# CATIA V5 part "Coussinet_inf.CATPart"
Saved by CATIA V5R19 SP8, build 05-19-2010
Part number: Coussinet_inf
Revision: ANY
Definition: UNKNOWN
Nomenclature: 7
Source: Unknown
Bounding box of the stored display mesh (mm): x -5 to 4.977, y -0.483 to 5, z 0 to 7
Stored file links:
  D:\Documents\1_Travail\2- 2I2D\1 - Cours et TD\2- TD\3-TD Assemblage\Pompe AirMan\Coussinet_inf.CATPart
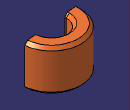
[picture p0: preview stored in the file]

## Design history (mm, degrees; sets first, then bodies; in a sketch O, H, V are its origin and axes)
Body1 "Chanfrein2" (main body)
  Solid1: solid without history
